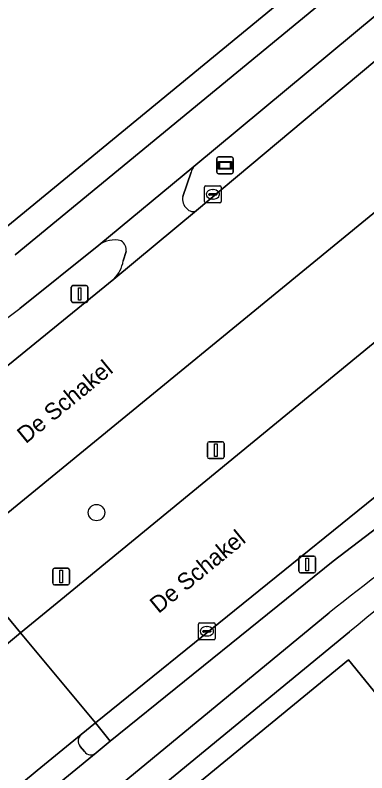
# Model space of a CAD drawing. Extents: x 156141 to 158132, y 385651 to 388333.
# Drawn here: x 157144.79 to 157165.79, y 386374.34 to 386419.56 of the extents above; entities that cross this region are included whole.
import ezdxf

# ---------------------------------------------------------------- set-up
doc = ezdxf.new("R2010")
doc.units = 0
for name, color, linetype in [('IMGEO_Afsluitpaal', 7, 'Continuous'), ('IMGEO_Berm_groen', 7, 'Continuous'), ('IMGEO_Boom', 7, 'Continuous'), ('IMGEO_Erf', 7, 'Continuous'), ('IMGEO_Fietspad_gesloten', 7, 'Continuous'), ('IMGEO_Fietspad_open', 7, 'Continuous'), ('IMGEO_Groenvoorziening', 7, 'Continuous'), ('IMGEO_Kolk', 7, 'Continuous'), ('IMGEO_Lichtmast', 7, 'Continuous'), ('IMGEO_Openbare_ruimte_label', 7, 'Continuous'), ('IMGEO_Rijbaan_lokaal_gesloten', 7, 'Continuous'), ('IMGEO_Verkeersbordpaal', 7, 'Continuous'), ('IMGEO_Voetpad_open', 7, 'Continuous'), ('IMGEO_Wegwijzer', 7, 'Continuous')]:
    doc.layers.add(name, color=color, linetype=linetype)

msp = doc.modelspace()

# ---------------------------------------------------------------- linework, layer by layer
at = {"layer": 'IMGEO_Afsluitpaal'}
for p, q in [((157147.039, 386385.648), (157147.039, 386386.448)), ((157147.039, 386386.448), (157147.039, 386385.648)), ((157147.139, 386386.548), (157147.929, 386386.548)), ((157147.929, 386386.548), (157147.139, 386386.548)), ((157148.029, 386386.448), (157148.029, 386385.648)), ((157148.029, 386385.648), (157148.029, 386386.448)), ((157147.929, 386385.548), (157147.139, 386385.548)), ((157147.139, 386385.548), (157147.929, 386385.548))]:
    msp.add_line(p, q, dxfattribs=at)
msp.add_lwpolyline([(157147.459, 386386.423), (157147.609, 386386.423), (157147.609, 386385.673), (157147.459, 386385.673), (157147.459, 386386.423)], dxfattribs=at)
for centre, start, end in [((157147.139, 386386.448), 90, 180), ((157147.139, 386386.448), 90, 180), ((157147.929, 386386.448), 0, 90), ((157147.929, 386386.448), 360, 90), ((157147.139, 386385.648), 180, 270), ((157147.139, 386385.648), 180, 270), ((157147.929, 386385.648), 270, 0), ((157147.929, 386385.648), 270, 0)]:
    msp.add_arc(centre, 0.1, start, end, dxfattribs=at)
at = {"layer": 'IMGEO_Berm_groen'}
for points in [[(157193.703, 386442.312), (157155.467, 386410.521)], [(157155.626, 386407.901), (157165.281, 386416.006), (157167.841, 386418.13), (157195.098, 386440.53)], [(157155.297, 386410.186), (157154.807, 386408.742)], [(157149.786, 386405.826), (157145.071, 386402.056)], [(157151.244, 386404.898), (157151.418, 386405.444)], [(157138.421, 386397.71), (157135.873, 386396.297), (157135.79, 386396.502), (157135.004, 386396.059), (157134.355, 386395.7), (157136.942, 386392.622), (157150.678, 386403.807)], [(157167.317, 386391.651), (157167.211, 386391.564), (157149.582, 386377.324), (157150.468, 386376.228), (157163.775, 386386.972), (157168.742, 386390.75)]]:
    msp.add_lwpolyline(points, dxfattribs=at)
msp.add_lwpolyline([(157171.716, 386404.521), (157173.857, 386406.278), (157176.215, 386408.236), (157172.303, 386412.729), (157169.899, 386410.784), (157167.798, 386409.063), (157143.686, 386389.309), (157141.268, 386387.328), (157145.103, 386382.684), (157147.51, 386384.659)], close=True, dxfattribs=at)
for centre, radius, start, end in [((157156.146, 386409.966), 0.877, 140.7268, 165.461), ((157155.503, 386408.571), 0.717, 166.1693, 230.7006), ((157155.401, 386408.276), 0.437, 216.4486, 301.0079), ((157150.729, 386404.565), 1.575, 75.7639, 126.7732), ((157150.743, 386405.523), 0.68, 353.3269, 56.7165), ((157149.313, 386405.207), 1.956, 314.265, 350.8953), ((157114.249, 386441.957), 50.419, 298.6475, 307.6845)]:
    msp.add_arc(centre, radius, start, end, dxfattribs=at)
at = {"layer": 'IMGEO_Boom'}
msp.add_circle((157149.649, 386389.868), 0.489, dxfattribs=at)
at = {"layer": 'IMGEO_Erf'}
for points in [[(157143.102, 386405.97), (157215.589, 386465.536), (157216.06, 386465.946), (157224.126, 386472.581), (157224.923, 386473.224), (157226.605, 386474.613), (157213.099, 386491.073)], [(157167.465, 386377.687), (157164.692, 386381.071), (157127.555, 386350.619)]]:
    msp.add_lwpolyline(points, dxfattribs=at)
at = {"layer": 'IMGEO_Fietspad_gesloten'}
for points in [[(157264.038, 386500), (157296.442, 386526.682), (157381.274, 386596.535), (157379.639, 386598.545), (157294.792, 386528.687), (157259.949, 386500), (157236.74, 386480.891), (157225.904, 386471.963), (157216.572, 386464.306), (157144.792, 386405.245)], [(157145.071, 386402.056), (157149.786, 386405.826), (157155.467, 386410.521), (157193.703, 386442.312), (157194.517, 386442.962), (157197.093, 386445.093), (157197.92, 386445.771), (157198.088, 386445.659), (157217.434, 386461.573), (157228.213, 386470.509), (157228.313, 386470.591), (157234.595, 386475.759), (157238.172, 386478.701), (157264.038, 386500)], [(157177.486, 386393.596), (157180.948, 386395.698), (157179.408, 386397.577), (157176.289, 386395.804), (157172.495, 386393.399), (157168.742, 386390.75), (157163.775, 386386.972), (157150.468, 386376.228), (157149.62, 386375.522), (157146.983, 386373.357), (157146.236, 386372.703), (157128.293, 386358.173), (157115.219, 386347.356), (157113.537, 386345.866), (157110.966, 386343.707), (157110.221, 386343.082), (157108.934, 386342.043), (157110.471, 386340.192), (157112.114, 386341.547), (157123.382, 386350.841), (157148.12, 386371.181)], [(157148.12, 386371.181), (157163.545, 386383.881)]]:
    msp.add_lwpolyline(points, dxfattribs=at)
for centre, radius, start, end in [((157114.249, 386441.957), 50.419, 298.6475, 307.6845), ((157239.982, 386289.055), 121.798, 120.87135, 128.87126)]:
    msp.add_arc(centre, radius, start, end, dxfattribs=at)
at = {"layer": 'IMGEO_Fietspad_open'}
for points in [[(157148.737, 386376.631), (157146.103, 386374.47), (157145.166, 386373.702), (157146.236, 386372.703), (157146.983, 386373.357), (157149.62, 386375.522)], [(157148.931, 386375.601), (157148.669, 386375.917)]]:
    msp.add_lwpolyline(points, dxfattribs=at)
for centre, radius, start, end in [((157149.063, 386376.24), 0.509, 129.7994, 219.3199), ((157149.315, 386375.907), 0.491, 218.5097, 308.4085)]:
    msp.add_arc(centre, radius, start, end, dxfattribs=at)
at = {"layer": 'IMGEO_Groenvoorziening'}
msp.add_lwpolyline([(157164.746, 386382.751), (157149.303, 386370.062), (157126.792, 386351.534), (157127.555, 386350.619), (157164.692, 386381.071), (157167.465, 386377.687)], dxfattribs=at)
msp.add_arc((157237.101, 386294.86), 113.842, 118.64795, 129.46246, dxfattribs=at)
at = {"layer": 'IMGEO_Kolk'}
for p, q in [((157156.093, 386408.439), (157156.093, 386409.291)), ((157156.168, 386409.365), (157157.02, 386409.365)), ((157157.094, 386409.291), (157157.094, 386408.439)), ((157156.352, 386408.859), (157156.352, 386408.871)), ((157156.79, 386408.822), (157156.392, 386408.822)), ((157156.395, 386408.908), (157156.793, 386408.908)), ((157156.581, 386409.145), (157156.606, 386409.145)), ((157156.836, 386408.871), (157156.836, 386408.859)), ((157157.02, 386408.365), (157156.168, 386408.365)), ((157156.604, 386408.585), (157156.579, 386408.585)), ((157155.736, 386382.357), (157155.736, 386383.209)), ((157155.811, 386383.283), (157156.663, 386383.283)), ((157156.224, 386383.063), (157156.249, 386383.063)), ((157156.737, 386383.209), (157156.737, 386382.357)), ((157155.995, 386382.777), (157155.995, 386382.789)), ((157156.433, 386382.74), (157156.035, 386382.74)), ((157156.038, 386382.826), (157156.436, 386382.826)), ((157156.479, 386382.789), (157156.479, 386382.777)), ((157156.663, 386382.283), (157155.811, 386382.283)), ((157156.247, 386382.503), (157156.222, 386382.503))]:
    msp.add_line(p, q, dxfattribs=at)
for points in [[(157156.093, 386408.439), (157156.093, 386409.291)], [(157156.168, 386409.365), (157157.02, 386409.365)], [(157157.094, 386409.291), (157157.094, 386408.439)], [(157157.02, 386408.365), (157156.168, 386408.365)], [(157155.736, 386382.357), (157155.736, 386383.209)], [(157155.811, 386383.283), (157156.663, 386383.283)], [(157156.737, 386383.209), (157156.737, 386382.357)], [(157156.663, 386382.283), (157155.811, 386382.283)]]:
    msp.add_lwpolyline(points, dxfattribs=at)
for centre, radius, start, end in [((157156.17, 386409.289), 0.0765, 91.552, 178.448), ((157156.17, 386409.289), 0.0765, 91.552, 178.448), ((157157.018, 386409.289), 0.0765, 1.552, 88.448), ((157157.018, 386409.289), 0.0765, 1.552, 88.448), ((157156.392, 386408.868), 0.0403, 85.8775, 175.7526), ((157156.389, 386408.858), 0.0366, 178.938, 274.7102), ((157156.793, 386408.865), 0.043, 264.8664, 352.4533), ((157156.797, 386408.87), 0.0386, 1.7309, 96.639), ((157156.17, 386408.441), 0.0765, 181.552, 268.448), ((157156.17, 386408.441), 0.0765, 181.552, 268.448), ((157157.018, 386408.441), 0.0765, 271.552, 358.448), ((157157.018, 386408.441), 0.0765, 271.552, 358.448), ((157155.813, 386383.207), 0.0765, 91.552, 178.448), ((157155.813, 386383.207), 0.0765, 91.552, 178.448), ((157156.661, 386383.207), 0.0765, 1.552, 88.448), ((157156.661, 386383.207), 0.0765, 1.552, 88.448), ((157156.035, 386382.786), 0.0403, 85.8775, 175.7526), ((157156.032, 386382.776), 0.0366, 178.938, 274.7102), ((157156.436, 386382.783), 0.043, 264.8664, 352.4533), ((157156.44, 386382.788), 0.0386, 1.7309, 96.639), ((157155.813, 386382.359), 0.0765, 181.552, 268.448), ((157155.813, 386382.359), 0.0765, 181.552, 268.448), ((157156.661, 386382.359), 0.0765, 271.552, 358.448), ((157156.661, 386382.359), 0.0765, 271.552, 358.448)]:
    msp.add_arc(centre, radius, start, end, dxfattribs=at)
for centre, major_axis, ratio, start_param, end_param in [((157156.58, 386408.865), (-0.387, 0.002), 0.722429, 4.712389, 7.853982), ((157156.605, 386408.865), (-0.39, 0.002), 0.717154, 1.570796, 4.712389), ((157156.223, 386382.783), (-0.387, 0.002), 0.722429, 4.712389, 7.853982), ((157156.248, 386382.783), (-0.39, 0.002), 0.717154, 1.570796, 4.712389)]:
    msp.add_ellipse(centre, major_axis=major_axis, ratio=ratio, start_param=start_param, end_param=end_param, dxfattribs=at)
at = {"layer": 'IMGEO_Lichtmast'}
for p, q in [((157148.245, 386403.416), (157149.035, 386403.416)), ((157149.035, 386403.416), (157148.245, 386403.416)), ((157148.145, 386402.516), (157148.145, 386403.316)), ((157148.145, 386403.316), (157148.145, 386402.516)), ((157149.135, 386403.316), (157149.135, 386402.516)), ((157149.135, 386402.516), (157149.135, 386403.316)), ((157149.035, 386402.416), (157148.245, 386402.416)), ((157148.245, 386402.416), (157149.035, 386402.416)), ((157161.734, 386386.373), (157161.734, 386387.173)), ((157161.734, 386387.173), (157161.734, 386386.373)), ((157161.834, 386387.273), (157162.624, 386387.273)), ((157162.624, 386387.273), (157161.834, 386387.273)), ((157162.724, 386387.173), (157162.724, 386386.373)), ((157162.724, 386386.373), (157162.724, 386387.173)), ((157162.624, 386386.273), (157161.834, 386386.273)), ((157161.834, 386386.273), (157162.624, 386386.273))]:
    msp.add_line(p, q, dxfattribs=at)
for points in [[(157148.565, 386403.291), (157148.715, 386403.291), (157148.715, 386402.541), (157148.565, 386402.541), (157148.565, 386403.291)], [(157162.154, 386387.148), (157162.304, 386387.148), (157162.304, 386386.398), (157162.154, 386386.398), (157162.154, 386387.148)]]:
    msp.add_lwpolyline(points, dxfattribs=at)
for centre, start, end in [((157148.245, 386403.316), 90, 180), ((157148.245, 386403.316), 90, 180), ((157149.035, 386403.316), 0, 90), ((157149.035, 386403.316), 360, 90), ((157148.245, 386402.516), 180, 270), ((157148.245, 386402.516), 180, 270), ((157149.035, 386402.516), 270, 0), ((157149.035, 386402.516), 270, 0), ((157161.834, 386387.173), 90, 180), ((157161.834, 386387.173), 90, 180), ((157162.624, 386387.173), 0, 90), ((157162.624, 386387.173), 360, 90), ((157161.834, 386386.373), 180, 270), ((157161.834, 386386.373), 180, 270), ((157162.624, 386386.373), 270, 0), ((157162.624, 386386.373), 270, 0)]:
    msp.add_arc(centre, 0.1, start, end, dxfattribs=at)
at = {"layer": 'IMGEO_Rijbaan_lokaal_gesloten'}
msp.add_lwpolyline([(157167.798, 386409.063), (157169.899, 386410.784), (157172.303, 386412.729), (157167.841, 386418.13), (157165.281, 386416.006), (157155.626, 386407.901), (157150.678, 386403.807), (157136.942, 386392.622), (157141.268, 386387.328), (157143.686, 386389.309)], close=True, dxfattribs=at)
for points in [[(157172.774, 386396.143), (157181.072, 386402.975), (157176.215, 386408.236), (157173.857, 386406.278), (157171.716, 386404.521), (157147.51, 386384.659), (157145.103, 386382.684), (157149.582, 386377.324), (157167.211, 386391.564)], [(157113.574, 386356.875), (157108.161, 386352.403), (157107.828, 386352.13), (157105.587, 386350.287), (157104.724, 386349.584), (157109.263, 386344.286), (157109.998, 386344.892), (157112.266, 386346.727), (157112.541, 386346.95), (157112.664, 386347.083), (157115.131, 386349.076), (157145.166, 386373.702), (157146.103, 386374.47), (157148.737, 386376.631), (157149.582, 386377.324), (157145.103, 386382.684), (157144.274, 386382.003), (157141.639, 386379.829), (157135.295, 386374.601)]]:
    msp.add_lwpolyline(points, dxfattribs=at)
at = {"layer": 'IMGEO_Verkeersbordpaal'}
for p, q in [((157156.275, 386393.198), (157156.275, 386393.998)), ((157156.275, 386393.998), (157156.275, 386393.198)), ((157156.375, 386394.098), (157157.165, 386394.098)), ((157157.165, 386394.098), (157156.375, 386394.098)), ((157157.265, 386393.998), (157157.265, 386393.198)), ((157157.265, 386393.198), (157157.265, 386393.998)), ((157157.165, 386393.098), (157156.375, 386393.098)), ((157156.375, 386393.098), (157157.165, 386393.098))]:
    msp.add_line(p, q, dxfattribs=at)
msp.add_lwpolyline([(157156.695, 386393.973), (157156.845, 386393.973), (157156.845, 386393.223), (157156.695, 386393.223), (157156.695, 386393.973)], dxfattribs=at)
for centre, start, end in [((157156.375, 386393.998), 90, 180), ((157156.375, 386393.998), 90, 180), ((157157.165, 386393.998), 0, 90), ((157157.165, 386393.998), 360, 90), ((157156.375, 386393.198), 180, 270), ((157156.375, 386393.198), 180, 270), ((157157.165, 386393.198), 270, 0), ((157157.165, 386393.198), 270, 0)]:
    msp.add_arc(centre, 0.1, start, end, dxfattribs=at)
at = {"layer": 'IMGEO_Voetpad_open'}
for points in [[(157144.792, 386405.245), (157216.572, 386464.306), (157215.589, 386465.536), (157143.102, 386405.97)], [(157155.467, 386410.521), (157149.786, 386405.826)], [(157154.807, 386408.742), (157155.297, 386410.186)], [(157150.678, 386403.807), (157155.626, 386407.901)], [(157151.418, 386405.444), (157151.244, 386404.898)], [(157144.274, 386382.003), (157145.103, 386382.684), (157141.268, 386387.328), (157140.443, 386386.652)], [(157163.545, 386383.881), (157148.12, 386371.181), (157123.382, 386350.841), (157112.114, 386341.547), (157110.471, 386340.192), (157107.758, 386338.314)], [(157149.303, 386370.062), (157164.746, 386382.751)], [(157150.468, 386376.228), (157149.582, 386377.324), (157148.737, 386376.631)], [(157149.62, 386375.522), (157150.468, 386376.228)], [(157148.669, 386375.917), (157148.931, 386375.601)]]:
    msp.add_lwpolyline(points, dxfattribs=at)
for centre, radius, start, end in [((157156.146, 386409.966), 0.877, 140.7268, 165.461), ((157155.503, 386408.571), 0.717, 166.1693, 230.7006), ((157155.401, 386408.276), 0.437, 216.4486, 301.0079), ((157150.729, 386404.565), 1.575, 75.7639, 126.7732), ((157150.743, 386405.523), 0.68, 353.3269, 56.7165), ((157149.313, 386405.207), 1.956, 314.265, 350.8953), ((157237.101, 386294.86), 113.842, 118.64795, 129.46246), ((157239.982, 386289.055), 121.798, 120.87135, 128.87126), ((157149.063, 386376.24), 0.509, 129.7994, 219.3199), ((157149.315, 386375.907), 0.491, 218.5097, 308.4085)]:
    msp.add_arc(centre, radius, start, end, dxfattribs=at)
at = {"layer": 'IMGEO_Wegwijzer'}
for p, q in [((157156.927, 386411.096), (157157.717, 386411.096)), ((157157.717, 386411.096), (157156.927, 386411.096)), ((157156.827, 386410.196), (157156.827, 386410.996)), ((157156.827, 386410.996), (157156.827, 386410.196)), ((157157.817, 386410.996), (157157.817, 386410.196)), ((157157.817, 386410.196), (157157.817, 386410.996)), ((157157.717, 386410.096), (157156.927, 386410.096)), ((157156.927, 386410.096), (157157.717, 386410.096))]:
    msp.add_line(p, q, dxfattribs=at)
for points in [[(157156.928, 386410.828), (157157.716, 386410.828), (157157.716, 386410.364), (157156.928, 386410.364), (157156.928, 386410.828)], [(157156.993, 386410.763), (157156.993, 386410.429), (157157.651, 386410.429), (157157.651, 386410.763), (157156.993, 386410.763)]]:
    msp.add_lwpolyline(points, dxfattribs=at)
for centre, start, end in [((157156.927, 386410.996), 90, 180), ((157156.927, 386410.996), 90, 180), ((157157.717, 386410.996), 0, 90), ((157157.717, 386410.996), 360, 90), ((157156.927, 386410.196), 180, 270), ((157156.927, 386410.196), 180, 270), ((157157.717, 386410.196), 270, 0), ((157157.717, 386410.196), 270, 0)]:
    msp.add_arc(centre, 0.1, start, end, dxfattribs=at)

# ---------------------------------------------------------------- texts
at = {"layer": 'IMGEO_Openbare_ruimte_label'}
for p in [(157145.426, 386393.946), (157153.35, 386383.808)]:
    msp.add_text('De Schakel', height=1, rotation=39.358, dxfattribs=at).set_placement(p)

doc.saveas('drawing.dxf')
